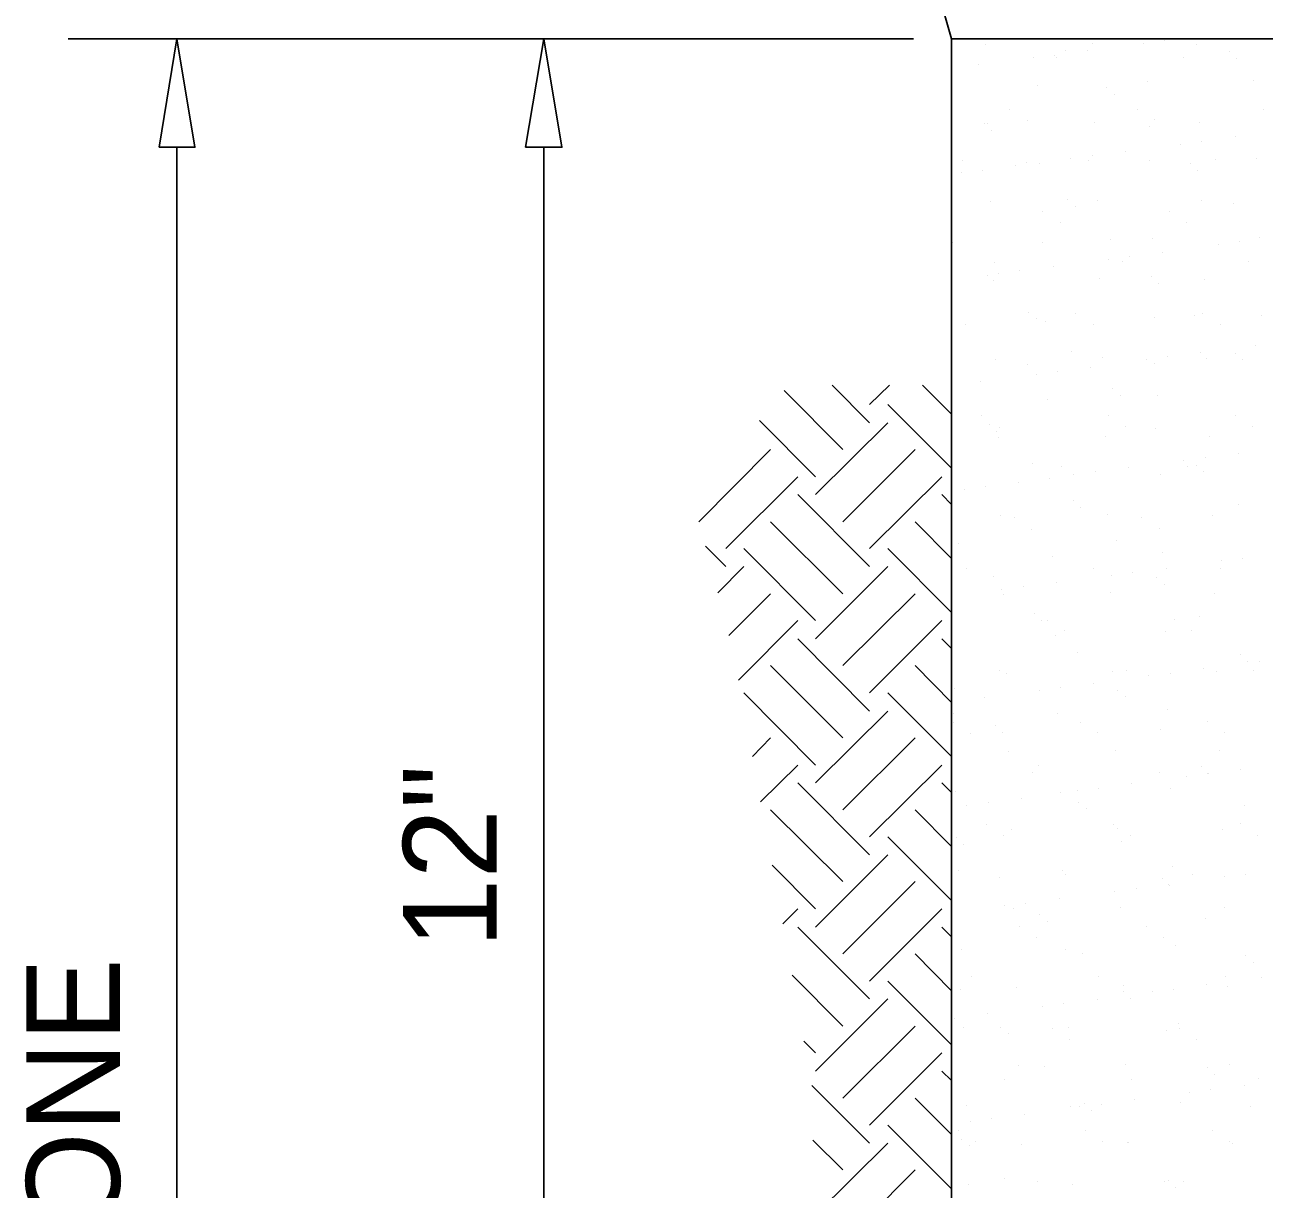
# Model space of a CAD drawing. Extents: x -118779 to -116979, y -104389 to -102939.
# Drawn here: x -117656.9 to -117577.5, y -103222.1 to -103147.5 of the extents above; entities that cross this region are included whole.
import ezdxf

# ---------------------------------------------------------------- set-up
doc = ezdxf.new("R2010")
doc.units = 0
for name, color, linetype in [('G-MARK', 7, 'Continuous'), ('G-TEXT', 7, 'Continuous'), ('Misc CnstDet(22)', 7, 'Continuous')]:
    doc.layers.add(name, color=color, linetype=linetype)

msp = doc.modelspace()

# ---------------------------------------------------------------- linework, layer by layer
at = {"layer": 'G-MARK'}
for p, q in [((-117599.93, -103148.355), (-117654.088, -103148.355)), ((-117647.13, -103155.313), (-117647.13, -103305.517)), ((-117623.616, -103155.313), (-117623.616, -103245.874))]:
    msp.add_line(p, q, dxfattribs=at)
at = {"layer": 'G-TEXT'}
for points in [[(-117648.261, -103155.313), (-117645.965, -103155.313), (-117647.13, -103148.355)], [(-117624.781, -103155.313), (-117622.45, -103155.313), (-117623.616, -103148.355)]]:
    msp.add_lwpolyline(points, close=True, dxfattribs=at)
at = {"layer": 'Misc CnstDet(22)'}
for p, q in [((-117597.496, -103148.355), (-117654.5, -102948.552)), ((-117599.93, -103148.355), (-117630.574, -103148.355)), ((-117597.496, -103148.355), (-117422.064, -103148.355)), ((-117597.496, -103148.355), (-117597.496, -103341.508)), ((-117597.496, -103148.355), (-117597.496, -103148.355)), ((-117597.496, -103148.355), (-117597.496, -103148.355)), ((-117588.481, -103148.663), (-117588.481, -103148.663)), ((-117585.225, -103148.663), (-117585.225, -103148.663)), ((-117583.854, -103148.492), (-117583.854, -103148.492)), ((-117581.797, -103148.697), (-117581.797, -103148.697)), ((-117595.302, -103148.732), (-117595.302, -103148.732)), ((-117590.881, -103149.417), (-117590.881, -103149.417)), ((-117590.161, -103149.109), (-117590.161, -103149.109)), ((-117588.756, -103149.109), (-117588.756, -103149.109)), ((-117579.706, -103149.177), (-117579.706, -103149.177)), ((-117595.782, -103150.034), (-117595.782, -103150.034)), ((-117592.252, -103149.589), (-117592.252, -103149.589)), ((-117590.778, -103149.589), (-117590.778, -103149.589)), ((-117582.654, -103149.554), (-117582.654, -103149.554)), ((-117579.226, -103149.623), (-117579.226, -103149.623)), ((-117578.13, -103151.028), (-117578.13, -103151.028)), ((-117592.012, -103151.371), (-117592.012, -103151.371)), ((-117587.556, -103151.474), (-117587.556, -103151.474)), ((-117584.951, -103151.097), (-117584.951, -103151.097)), ((-117587.076, -103151.92), (-117587.076, -103151.92)), ((-117593.76, -103152.879), (-117593.76, -103152.879)), ((-117585.602, -103152.879), (-117585.602, -103152.879)), ((-117577.478, -103152.879), (-117577.478, -103152.879)), ((-117595.405, -103153.771), (-117595.405, -103153.771)), ((-117595.165, -103153.771), (-117595.165, -103153.771)), ((-117594.925, -103154.216), (-117594.925, -103154.216)), ((-117592.629, -103153.599), (-117592.629, -103153.599)), ((-117588.31, -103153.702), (-117588.31, -103153.702)), ((-117584.814, -103154.01), (-117584.814, -103154.01)), ((-117584.505, -103153.565), (-117584.505, -103153.565)), ((-117581.626, -103153.702), (-117581.626, -103153.702)), ((-117581.454, -103154.936), (-117581.454, -103154.936)), ((-117579.329, -103154.627), (-117579.329, -103154.627)), ((-117586.356, -103155.553), (-117586.356, -103155.553)), ((-117582.826, -103155.107), (-117582.826, -103155.107)), ((-117596.811, -103156.136), (-117596.811, -103156.136)), ((-117593.383, -103156.478), (-117593.383, -103156.478)), ((-117592.663, -103156.307), (-117592.663, -103156.307)), ((-117591.84, -103156.376), (-117591.84, -103156.376)), ((-117589.852, -103156.033), (-117589.852, -103156.033)), ((-117588.687, -103156.136), (-117588.687, -103156.136)), ((-117588.481, -103155.861), (-117588.481, -103155.861)), ((-117584.779, -103156.136), (-117584.779, -103156.136)), ((-117582.209, -103156.376), (-117582.209, -103156.376)), ((-117580.563, -103156.101), (-117580.563, -103156.101)), ((-117577.958, -103156.033), (-117577.958, -103156.033)), ((-117596.879, -103156.958), (-117596.879, -103156.958)), ((-117595.508, -103156.787), (-117595.508, -103156.787)), ((-117581.729, -103156.821), (-117581.729, -103156.821)), ((-117594.994, -103158.809), (-117594.994, -103158.809)), ((-117590.058, -103158.672), (-117590.058, -103158.672)), ((-117588.139, -103158.707), (-117588.139, -103158.707)), ((-117581.454, -103158.741), (-117581.454, -103158.741)), ((-117579.432, -103158.912), (-117579.432, -103158.912)), ((-117591.635, -103159.426), (-117591.635, -103159.426)), ((-117589.578, -103159.118), (-117589.578, -103159.118)), ((-117583.511, -103159.426), (-117583.511, -103159.426)), ((-117590.538, -103160.146), (-117590.538, -103160.146)), ((-117582.414, -103160.112), (-117582.414, -103160.112)), ((-117597.428, -103161.414), (-117597.428, -103161.414)), ((-117591.669, -103161.414), (-117591.669, -103161.414)), ((-117587.282, -103161.209), (-117587.282, -103161.209)), ((-117584.608, -103161.174), (-117584.608, -103161.174)), ((-117579.055, -103161.38), (-117579.055, -103161.38)), ((-117577.787, -103161.072), (-117577.787, -103161.072)), ((-117583.957, -103162.031), (-117583.957, -103162.031)), ((-117580.392, -103161.552), (-117580.392, -103161.552)), ((-117594.72, -103162.683), (-117594.72, -103162.683)), ((-117590.984, -103162.957), (-117590.984, -103162.957)), ((-117587.419, -103162.477), (-117587.419, -103162.477)), ((-117586.562, -103162.648), (-117586.562, -103162.648)), ((-117586.082, -103162.306), (-117586.082, -103162.306)), ((-117578.438, -103162.648), (-117578.438, -103162.648)), ((-117595.165, -103163.505), (-117595.165, -103163.505)), ((-117594.48, -103163.403), (-117594.48, -103163.403)), ((-117593.109, -103163.231), (-117593.109, -103163.231)), ((-117588.001, -103163.745), (-117588.001, -103163.745)), ((-117584.711, -103163.574), (-117584.711, -103163.574)), ((-117581.317, -103163.78), (-117581.317, -103163.78)), ((-117594.823, -103163.848), (-117594.823, -103163.848)), ((-117584.231, -103164.02), (-117584.231, -103164.02)), ((-117592.56, -103165.87), (-117592.56, -103165.87)), ((-117589.544, -103165.973), (-117589.544, -103165.973)), ((-117581.934, -103166.11), (-117581.934, -103166.11)), ((-117581.386, -103165.973), (-117581.386, -103165.973)), ((-117577.615, -103166.11), (-117577.615, -103166.11)), ((-117596.571, -103166.693), (-117596.571, -103166.693)), ((-117592.08, -103166.316), (-117592.08, -103166.316)), ((-117591.498, -103166.453), (-117591.498, -103166.453)), ((-117588.413, -103166.693), (-117588.413, -103166.693)), ((-117584.471, -103166.213), (-117584.471, -103166.213)), ((-117580.289, -103166.659), (-117580.289, -103166.659)), ((-117589.784, -103168.407), (-117589.784, -103168.407)), ((-117581.557, -103168.476), (-117581.557, -103168.476)), ((-117579.329, -103168.51), (-117579.329, -103168.51)), ((-117577.992, -103167.996), (-117577.992, -103167.996)), ((-117594.651, -103168.887), (-117594.651, -103168.887)), ((-117592.595, -103169.23), (-117592.595, -103169.23)), ((-117587.83, -103168.784), (-117587.83, -103168.784)), ((-117585.019, -103168.921), (-117585.019, -103168.921)), ((-117584.471, -103169.195), (-117584.471, -103169.195)), ((-117583.682, -103168.75), (-117583.682, -103168.75)), ((-117581.146, -103168.818), (-117581.146, -103168.818)), ((-117578.849, -103168.921), (-117578.849, -103168.921)), ((-117592.046, -103169.847), (-117592.046, -103169.847)), ((-117590.709, -103169.675), (-117590.709, -103169.675)), ((-117588.584, -103169.401), (-117588.584, -103169.401)), ((-117604.455, -103174.68), (-117608.225, -103170.909)), ((-117602.741, -103172.966), (-117605.14, -103170.566)), ((-117602.741, -103171.8), (-117601.472, -103170.566)), ((-117597.496, -103172.417), (-117599.347, -103170.566)), ((-117595.611, -103170.327), (-117595.611, -103170.327)), ((-117587.179, -103170.772), (-117587.179, -103170.772)), ((-117591.361, -103171.492), (-117591.361, -103171.492)), ((-117586.699, -103171.218), (-117586.699, -103171.218)), ((-117584.299, -103171.218), (-117584.299, -103171.218)), ((-117597.496, -103175.88), (-117601.575, -103171.8)), ((-117595.542, -103172.52), (-117595.542, -103172.52)), ((-117587.419, -103172.52), (-117587.419, -103172.52)), ((-117579.295, -103172.486), (-117579.295, -103172.486)), ((-117606.203, -103176.428), (-117609.802, -103172.829)), ((-117606.203, -103177.559), (-117601.575, -103172.966)), ((-117595.063, -103173.069), (-117595.063, -103173.069)), ((-117594.446, -103173.24), (-117594.446, -103173.24)), ((-117586.322, -103173.206), (-117586.322, -103173.206)), ((-117584.437, -103173.309), (-117584.437, -103173.309)), ((-117578.198, -103173.206), (-117578.198, -103173.206)), ((-117594.583, -103173.514), (-117594.583, -103173.514)), ((-117594.48, -103173.891), (-117594.48, -103173.891)), ((-117587.659, -103173.823), (-117587.659, -103173.823)), ((-117580.975, -103173.857), (-117580.975, -103173.857)), ((-117613.675, -103179.307), (-117609.082, -103174.68)), ((-117604.455, -103179.307), (-117599.827, -103174.68)), ((-117592.286, -103175.605), (-117592.286, -103175.605)), ((-117582.62, -103175.365), (-117582.62, -103175.365)), ((-117581.831, -103175.708), (-117581.831, -103175.708)), ((-117581.249, -103175.194), (-117581.249, -103175.194)), ((-117579.124, -103174.92), (-117579.124, -103174.92)), ((-117611.961, -103181.021), (-117607.334, -103176.428)), ((-117602.741, -103181.021), (-117598.113, -103176.428)), ((-117590.469, -103175.742), (-117590.469, -103175.742)), ((-117589.647, -103176.291), (-117589.647, -103176.291)), ((-117588.276, -103176.119), (-117588.276, -103176.119)), ((-117586.15, -103175.845), (-117586.15, -103175.845)), ((-117584.128, -103176.257), (-117584.128, -103176.257)), ((-117582.346, -103175.742), (-117582.346, -103175.742)), ((-117581.352, -103176.119), (-117581.352, -103176.119)), ((-117596.674, -103177.216), (-117596.674, -103177.216)), ((-117595.337, -103177.045), (-117595.337, -103177.045)), ((-117593.212, -103176.771), (-117593.212, -103176.771)), ((-117591.189, -103176.531), (-117591.189, -103176.531)), ((-117602.741, -103182.187), (-117607.334, -103177.559)), ((-117597.496, -103178.21), (-117598.113, -103177.559)), ((-117589.681, -103177.97), (-117589.681, -103177.97)), ((-117589.201, -103178.416), (-117589.201, -103178.416)), ((-117587.487, -103178.862), (-117587.487, -103178.862)), ((-117579.089, -103178.21), (-117579.089, -103178.21)), ((-117604.455, -103183.935), (-117609.082, -103179.307)), ((-117597.496, -103181.672), (-117599.827, -103179.307)), ((-117594.343, -103178.93), (-117594.343, -103178.93)), ((-117593.452, -103179.067), (-117593.452, -103179.067)), ((-117585.293, -103179.067), (-117585.293, -103179.067)), ((-117580.803, -103178.896), (-117580.803, -103178.896)), ((-117592.355, -103179.787), (-117592.355, -103179.787)), ((-117584.197, -103179.753), (-117584.197, -103179.753)), ((-117611.961, -103182.187), (-117613.264, -103180.884)), ((-117606.203, -103185.649), (-117610.796, -103181.021)), ((-117597.496, -103185.134), (-117601.575, -103181.021)), ((-117597.051, -103180.713), (-117597.051, -103180.713)), ((-117586.939, -103180.507), (-117586.939, -103180.507)), ((-117591.018, -103181.57), (-117591.018, -103181.57)), ((-117583.957, -103181.295), (-117583.957, -103181.295)), ((-117580.22, -103181.809), (-117580.22, -103181.809)), ((-117578.849, -103181.638), (-117578.849, -103181.638)), ((-117612.475, -103183.866), (-117610.796, -103182.187)), ((-117606.203, -103186.814), (-117601.575, -103182.187)), ((-117596.502, -103182.324), (-117596.502, -103182.324)), ((-117594.788, -103182.804), (-117594.788, -103182.804)), ((-117588.378, -103182.289), (-117588.378, -103182.289)), ((-117587.247, -103182.735), (-117587.247, -103182.735)), ((-117585.876, -103182.564), (-117585.876, -103182.564)), ((-117583.751, -103182.289), (-117583.751, -103182.289)), ((-117580.255, -103182.289), (-117580.255, -103182.289)), ((-117592.903, -103183.489), (-117592.903, -103183.489)), ((-117590.778, -103183.215), (-117590.778, -103183.215)), ((-117584.334, -103182.906), (-117584.334, -103182.906)), ((-117583.854, -103183.318), (-117583.854, -103183.318)), ((-117611.756, -103186.608), (-117609.082, -103183.935)), ((-117604.455, -103188.528), (-117599.827, -103183.935)), ((-117594.274, -103183.66), (-117594.274, -103183.66)), ((-117594.171, -103183.969), (-117594.171, -103183.969)), ((-117587.316, -103183.866), (-117587.316, -103183.866)), ((-117580.632, -103183.9), (-117580.632, -103183.9)), ((-117592.183, -103185.169), (-117592.183, -103185.169)), ((-117611.139, -103189.453), (-117607.334, -103185.649)), ((-117602.741, -103190.276), (-117598.113, -103185.649)), ((-117591.703, -103185.614), (-117591.703, -103185.614)), ((-117591.326, -103185.614), (-117591.326, -103185.614)), ((-117583.203, -103185.58), (-117583.203, -103185.58)), ((-117581.592, -103185.409), (-117581.592, -103185.409)), ((-117602.741, -103191.441), (-117607.334, -103186.814)), ((-117597.496, -103187.431), (-117598.113, -103186.814)), ((-117590.846, -103186.574), (-117590.846, -103186.574)), ((-117590.229, -103186.3), (-117590.229, -103186.3)), ((-117583.785, -103186.334), (-117583.785, -103186.334)), ((-117582.106, -103186.3), (-117582.106, -103186.3)), ((-117589.441, -103187.705), (-117589.441, -103187.705)), ((-117578.986, -103187.808), (-117578.986, -103187.808)), ((-117578.507, -103188.254), (-117578.507, -103188.254)), ((-117577.787, -103188.254), (-117577.787, -103188.254)), ((-117604.455, -103193.155), (-117609.082, -103188.528)), ((-117597.496, -103190.893), (-117599.827, -103188.528)), ((-117594.411, -103188.871), (-117594.411, -103188.871)), ((-117594, -103189.008), (-117594, -103189.008)), ((-117587.179, -103188.905), (-117587.179, -103188.905)), ((-117586.253, -103188.836), (-117586.253, -103188.836)), ((-117584.848, -103189.179), (-117584.848, -103189.179)), ((-117583.477, -103189.008), (-117583.477, -103189.008)), ((-117581.352, -103188.734), (-117581.352, -103188.734)), ((-117580.495, -103188.939), (-117580.495, -103188.939)), ((-117578.13, -103188.836), (-117578.13, -103188.836)), ((-117590.504, -103189.933), (-117590.504, -103189.933)), ((-117588.378, -103189.659), (-117588.378, -103189.659)), ((-117606.203, -103194.903), (-117610.796, -103190.276)), ((-117597.496, -103194.355), (-117601.575, -103190.276)), ((-117597.291, -103190.002), (-117597.291, -103190.002)), ((-117595.405, -103190.585), (-117595.405, -103190.585)), ((-117591.875, -103190.105), (-117591.875, -103190.105)), ((-117586.836, -103190.105), (-117586.836, -103190.105)), ((-117586.356, -103190.516), (-117586.356, -103190.516)), ((-117606.203, -103196.035), (-117601.575, -103191.441)), ((-117597.359, -103191.579), (-117597.359, -103191.579)), ((-117583.648, -103191.373), (-117583.648, -103191.373)), ((-117597.359, -103192.161), (-117597.359, -103192.161)), ((-117594.686, -103192.367), (-117594.686, -103192.367)), ((-117590.675, -103191.613), (-117590.675, -103191.613)), ((-117589.235, -103192.161), (-117589.235, -103192.161)), ((-117581.077, -103192.127), (-117581.077, -103192.127)), ((-117610.247, -103194.355), (-117609.082, -103193.155)), ((-117604.455, -103197.783), (-117599.827, -103193.155)), ((-117596.262, -103192.881), (-117596.262, -103192.881)), ((-117594.206, -103192.813), (-117594.206, -103192.813)), ((-117588.139, -103192.847), (-117588.139, -103192.847)), ((-117584.094, -103192.607), (-117584.094, -103192.607)), ((-117579.98, -103192.847), (-117579.98, -103192.847)), ((-117587.007, -103193.944), (-117587.007, -103193.944)), ((-117593.829, -103194.047), (-117593.829, -103194.047)), ((-117580.323, -103193.978), (-117580.323, -103193.978)), ((-117609.733, -103197.269), (-117607.334, -103194.903)), ((-117602.741, -103199.497), (-117598.113, -103194.903)), ((-117592.286, -103195.383), (-117592.286, -103195.383)), ((-117591.943, -103194.903), (-117591.943, -103194.903)), ((-117584.162, -103195.383), (-117584.162, -103195.383)), ((-117581.489, -103195.006), (-117581.489, -103195.006)), ((-117581.077, -103195.452), (-117581.077, -103195.452)), ((-117581.009, -103195.452), (-117581.009, -103195.452)), ((-117578.952, -103195.178), (-117578.952, -103195.178)), ((-117602.741, -103200.662), (-117607.334, -103196.035)), ((-117597.496, -103196.652), (-117598.113, -103196.035)), ((-117585.979, -103196.103), (-117585.979, -103196.103)), ((-117582.414, -103195.623), (-117582.414, -103195.623)), ((-117597.222, -103196.617), (-117597.222, -103196.617)), ((-117593.006, -103197.029), (-117593.006, -103197.029)), ((-117590.538, -103196.652), (-117590.538, -103196.652)), ((-117589.441, -103196.549), (-117589.441, -103196.549)), ((-117588.104, -103196.377), (-117588.104, -103196.377)), ((-117583.477, -103196.412), (-117583.477, -103196.412)), ((-117604.455, -103202.376), (-117609.082, -103197.783)), ((-117597.496, -103200.114), (-117599.827, -103197.783)), ((-117596.502, -103197.474), (-117596.502, -103197.474)), ((-117595.131, -103197.303), (-117595.131, -103197.303)), ((-117589.338, -103197.303), (-117589.338, -103197.303)), ((-117588.858, -103197.714), (-117588.858, -103197.714)), ((-117578.746, -103197.509), (-117578.746, -103197.509)), ((-117595.234, -103198.708), (-117595.234, -103198.708)), ((-117587.11, -103198.708), (-117587.11, -103198.708)), ((-117578.986, -103198.674), (-117578.986, -103198.674)), ((-117597.496, -103203.576), (-117601.575, -103199.497)), ((-117594.137, -103199.394), (-117594.137, -103199.394)), ((-117593.657, -103199.051), (-117593.657, -103199.051)), ((-117586.836, -103198.982), (-117586.836, -103198.982)), ((-117586.013, -103199.394), (-117586.013, -103199.394)), ((-117580.152, -103199.017), (-117580.152, -103199.017)), ((-117577.89, -103199.394), (-117577.89, -103199.394)), ((-117597.188, -103199.565), (-117597.188, -103199.565)), ((-117596.708, -103200.011), (-117596.708, -103200.011)), ((-117586.596, -103199.805), (-117586.596, -103199.805)), ((-117606.203, -103205.29), (-117601.575, -103200.662)), ((-117606.203, -103204.124), (-117608.979, -103201.313)), ((-117597.051, -103201.656), (-117597.051, -103201.656)), ((-117590.367, -103201.69), (-117590.367, -103201.69)), ((-117583.305, -103201.416), (-117583.305, -103201.416)), ((-117578.644, -103201.896), (-117578.644, -103201.896)), ((-117604.455, -103207.003), (-117599.827, -103202.376)), ((-117594.446, -103202.102), (-117594.446, -103202.102)), ((-117590.195, -103201.93), (-117590.195, -103201.93)), ((-117583.991, -103202.205), (-117583.991, -103202.205)), ((-117583.58, -103202.547), (-117583.58, -103202.547)), ((-117583.511, -103202.65), (-117583.511, -103202.65)), ((-117582.037, -103201.93), (-117582.037, -103201.93)), ((-117580.015, -103202.067), (-117580.015, -103202.067)), ((-117590.606, -103203.473), (-117590.606, -103203.473)), ((-117587.042, -103202.993), (-117587.042, -103202.993)), ((-117585.671, -103202.822), (-117585.671, -103202.822)), ((-117608.294, -103205.084), (-117607.334, -103204.124)), ((-117602.741, -103208.752), (-117598.113, -103204.124)), ((-117594.069, -103203.918), (-117594.069, -103203.918)), ((-117593.52, -103204.09), (-117593.52, -103204.09)), ((-117592.732, -103203.747), (-117592.732, -103203.747)), ((-117586.665, -103204.021), (-117586.665, -103204.021)), ((-117579.98, -103204.056), (-117579.98, -103204.056)), ((-117591.84, -103204.501), (-117591.84, -103204.501)), ((-117591.361, -103204.912), (-117591.361, -103204.912)), ((-117581.214, -103204.707), (-117581.214, -103204.707)), ((-117602.741, -103209.883), (-117607.334, -103205.29)), ((-117597.496, -103205.907), (-117598.113, -103205.29)), ((-117593.143, -103205.255), (-117593.143, -103205.255)), ((-117585.019, -103205.221), (-117585.019, -103205.221)), ((-117592.046, -103205.941), (-117592.046, -103205.941)), ((-117583.888, -103205.941), (-117583.888, -103205.941)), ((-117583.134, -103206.455), (-117583.134, -103206.455)), ((-117597.496, -103209.369), (-117599.827, -103207.003)), ((-117596.879, -103206.695), (-117596.879, -103206.695)), ((-117590.195, -103206.729), (-117590.195, -103206.729)), ((-117589.098, -103207.003), (-117589.098, -103207.003)), ((-117578.644, -103207.106), (-117578.644, -103207.106)), ((-117578.164, -103207.552), (-117578.164, -103207.552)), ((-117604.455, -103211.631), (-117607.711, -103208.375)), ((-117597.496, -103212.831), (-117601.575, -103208.752)), ((-117596.194, -103208.477), (-117596.194, -103208.477)), ((-117588.07, -103208.477), (-117588.07, -103208.477)), ((-117581.146, -103208.991), (-117581.146, -103208.991)), ((-117579.946, -103208.477), (-117579.946, -103208.477)), ((-117577.615, -103208.512), (-117577.615, -103208.512)), ((-117596.948, -103209.3), (-117596.948, -103209.3)), ((-117593.349, -103209.129), (-117593.349, -103209.129)), ((-117586.493, -103209.06), (-117586.493, -103209.06)), ((-117586.493, -103209.403), (-117586.493, -103209.403)), ((-117586.013, -103209.848), (-117586.013, -103209.848)), ((-117584.642, -103209.437), (-117584.642, -103209.437)), ((-117583.271, -103209.266), (-117583.271, -103209.266)), ((-117579.809, -103209.094), (-117579.809, -103209.094)), ((-117606.203, -103214.51), (-117601.575, -103209.883)), ((-117591.669, -103210.363), (-117591.669, -103210.363)), ((-117590.298, -103210.191), (-117590.298, -103210.191)), ((-117588.173, -103209.917), (-117588.173, -103209.917)), ((-117597.325, -103211.117), (-117597.325, -103211.117)), ((-117595.2, -103210.842), (-117595.2, -103210.842)), ((-117604.455, -103216.258), (-117599.827, -103211.631)), ((-117596.708, -103211.734), (-117596.708, -103211.734)), ((-117594.343, -103211.699), (-117594.343, -103211.699)), ((-117593.863, -103212.111), (-117593.863, -103212.111)), ((-117591.018, -103211.802), (-117591.018, -103211.802)), ((-117590.024, -103211.734), (-117590.024, -103211.734)), ((-117583.717, -103211.905), (-117583.717, -103211.905)), ((-117582.963, -103211.494), (-117582.963, -103211.494)), ((-117582.894, -103211.768), (-117582.894, -103211.768)), ((-117606.203, -103213.345), (-117606.957, -103212.591)), ((-117589.921, -103212.488), (-117589.921, -103212.488)), ((-117581.797, -103212.488), (-117581.797, -103212.488)), ((-117602.741, -103217.972), (-117598.113, -103213.345)), ((-117597.496, -103215.127), (-117598.113, -103214.51)), ((-117593.177, -103214.167), (-117593.177, -103214.167)), ((-117591.566, -103214.202), (-117591.566, -103214.202)), ((-117586.356, -103214.065), (-117586.356, -103214.065)), ((-117581.112, -103214.305), (-117581.112, -103214.305)), ((-117579.672, -103214.099), (-117579.672, -103214.099)), ((-117594.103, -103215.024), (-117594.103, -103215.024)), ((-117585.979, -103215.024), (-117585.979, -103215.024)), ((-117580.632, -103214.75), (-117580.632, -103214.75)), ((-117577.821, -103214.99), (-117577.821, -103214.99)), ((-117602.741, -103219.138), (-117606.443, -103215.436)), ((-117582.243, -103215.881), (-117582.243, -103215.881)), ((-117580.872, -103215.71), (-117580.872, -103215.71)), ((-117578.746, -103215.436), (-117578.746, -103215.436)), ((-117597.496, -103218.589), (-117599.827, -103216.258)), ((-117596.536, -103216.738), (-117596.536, -103216.738)), ((-117589.852, -103216.772), (-117589.852, -103216.772)), ((-117589.27, -103216.807), (-117589.27, -103216.807)), ((-117588.995, -103216.601), (-117588.995, -103216.601)), ((-117587.899, -103216.635), (-117587.899, -103216.635)), ((-117585.773, -103216.361), (-117585.773, -103216.361)), ((-117582.826, -103216.533), (-117582.826, -103216.533)), ((-117578.369, -103216.807), (-117578.369, -103216.807)), ((-117596.297, -103217.732), (-117596.297, -103217.732)), ((-117594.925, -103217.561), (-117594.925, -103217.561)), ((-117592.8, -103217.287), (-117592.8, -103217.287)), ((-117588.516, -103217.047), (-117588.516, -103217.047)), ((-117597.496, -103222.051), (-117601.575, -103217.972)), ((-117597.051, -103218.349), (-117597.051, -103218.349)), ((-117588.927, -103218.315), (-117588.927, -103218.315)), ((-117580.803, -103218.315), (-117580.803, -103218.315)), ((-117604.455, -103220.851), (-117606.374, -103218.932)), ((-117606.203, -103223.731), (-117601.575, -103219.138)), ((-117596.845, -103218.898), (-117596.845, -103218.898)), ((-117596.365, -103219.309), (-117596.365, -103219.309)), ((-117595.954, -103219.035), (-117595.954, -103219.035)), ((-117593.006, -103219.206), (-117593.006, -103219.206)), ((-117587.83, -103219.035), (-117587.83, -103219.035)), ((-117586.219, -103219.103), (-117586.219, -103219.103)), ((-117586.185, -103219.103), (-117586.185, -103219.103)), ((-117579.672, -103219.001), (-117579.672, -103219.001)), ((-117579.501, -103219.138), (-117579.501, -103219.138)), ((-117604.455, -103225.479), (-117599.827, -103220.851)), ((-117594.069, -103221.4), (-117594.069, -103221.4)), ((-117591.978, -103221.571), (-117591.978, -103221.571)), ((-117583.854, -103221.571), (-117583.854, -103221.571)), ((-117583.614, -103221.503), (-117583.614, -103221.503)), ((-117582.654, -103221.571), (-117582.654, -103221.571)), ((-117596.399, -103221.777), (-117596.399, -103221.777)), ((-117589.715, -103221.811), (-117589.715, -103221.811)), ((-117583.134, -103221.948), (-117583.134, -103221.948))]:
    msp.add_line(p, q, dxfattribs=at)

# ---------------------------------------------------------------- texts
for s, p in [('12"', (-117626.629, -103206.647)), ('PIPE ZONE', (-117650.774, -103250.083))]:
    msp.add_text(s, height=6, rotation=90, dxfattribs=at).set_placement(p)

doc.saveas('drawing.dxf')
